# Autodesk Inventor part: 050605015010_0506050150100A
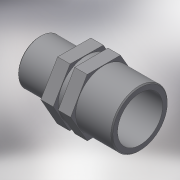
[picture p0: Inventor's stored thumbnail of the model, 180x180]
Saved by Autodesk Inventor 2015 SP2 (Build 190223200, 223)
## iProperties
Created: 2017-05
Part Number: 050605015010_0506050150100A
Material: Generic
Description: PLASSON REDUCING NIPPLE 1.1/2"-1"
Document SubType Name: Modeling
Designer: KIM
Density: 1 g/cm^3
Appearance: Default
Author: KIM
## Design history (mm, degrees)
derived "050605.ipt"
feature "Solid1::050605.ipt"
tag "TaggingFeature1"
body "Solid1"
other parameters: "d0" = 57, "d1" = 47.803, "d5" = 21, "d6" = 5.7, "d8" = 0.57, "d12" = 0, "d14" = 33.249, "d15" = 26.5992, "d16" = 38.2424, "d17" = 19, "d18" = 2.85, "d21" = 0, "H_" = 57, "R_" = 47.803, "l_" = 21, "R_1" = 33.249, "l_1" = 19
